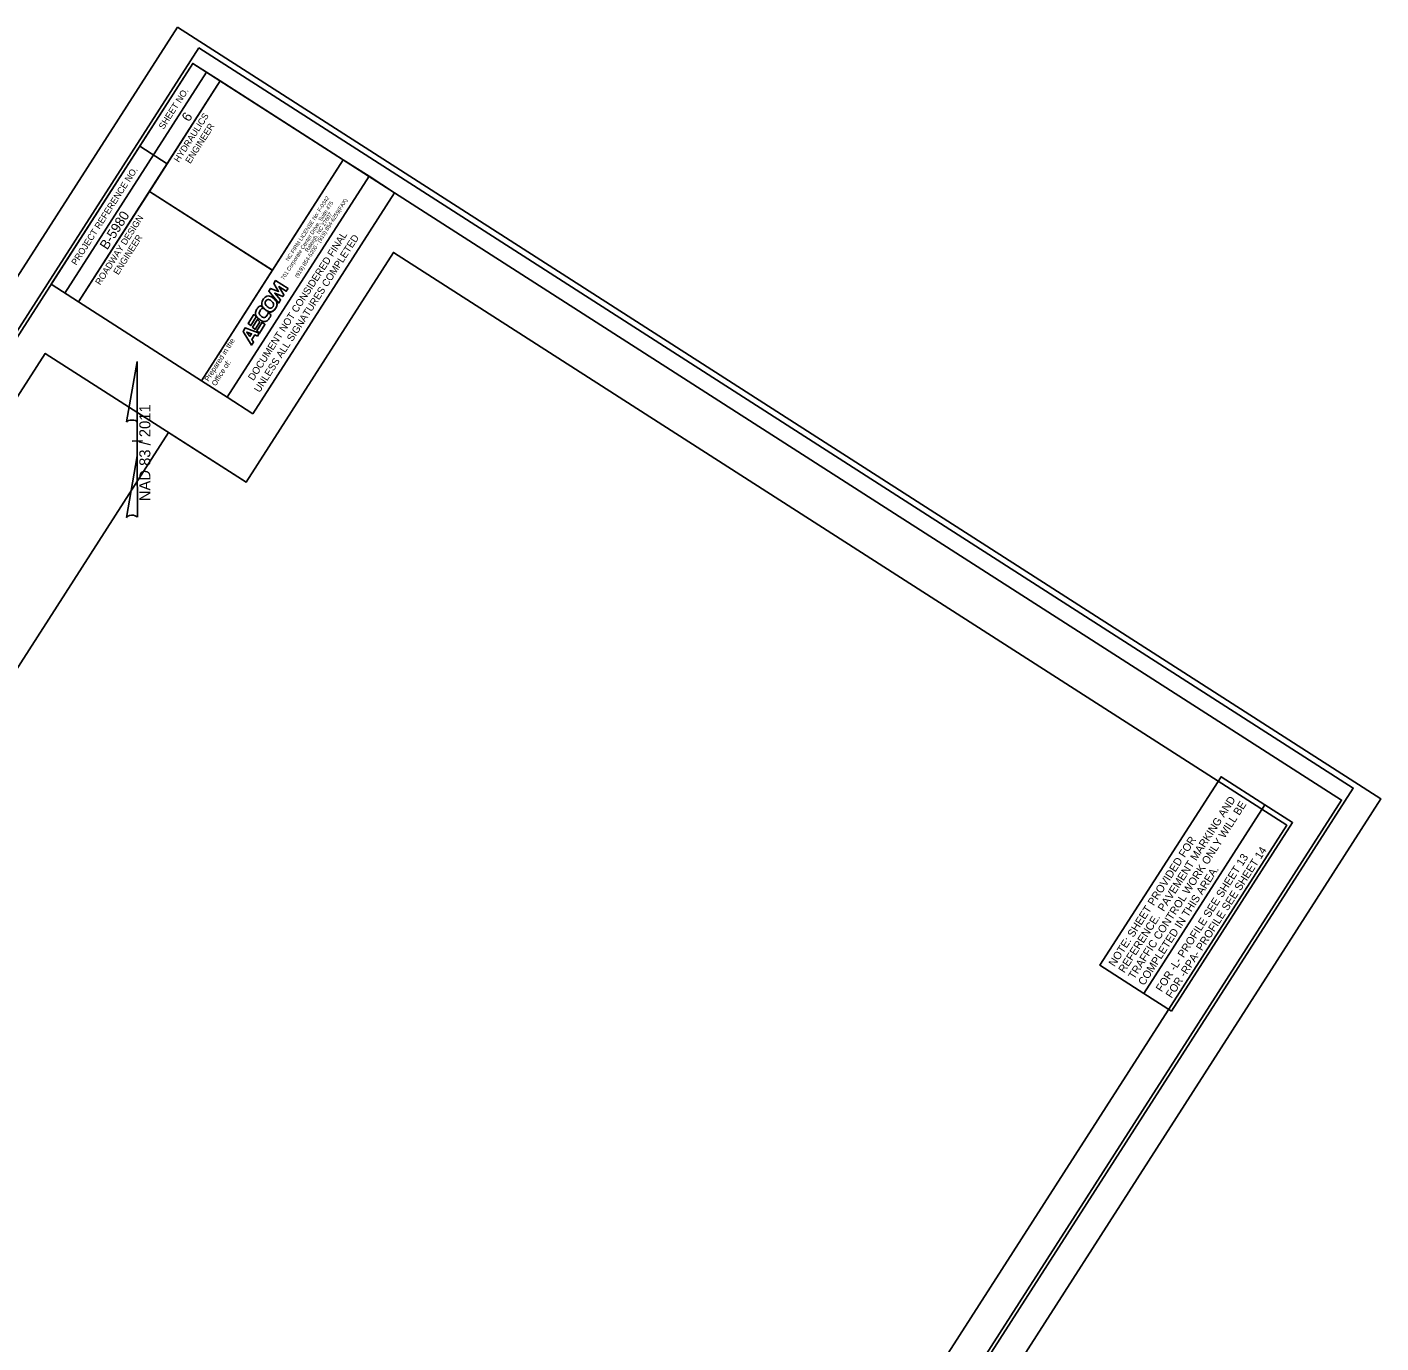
# Model space of a CAD drawing. Extents: x 2348257 to 2350100, y 844892 to 846917.
# Drawn here: x 2349059 to 2350100, y 845904 to 846917 of the extents above; entities that cross this region are included whole.
import ezdxf

# ---------------------------------------------------------------- set-up
doc = ezdxf.new("R2010")
doc.units = 0
for name, color, linetype in [('Default', 7, 'Continuous'), ('Old_Level_49', 7, 'Continuous'), ('Prop DSN Text', 7, 'Continuous'), ('Prop North Arrow NAD83 for Plan Sheets CELL', 7, 'Continuous'), ('Prop PFL Text', 7, 'Continuous'), ('Sheet Border Standard 30in CELL', 7, 'Continuous'), ('Sheet Clip Boundary CELL', 7, 'Continuous'), ('Sheet Data Field CELL', 7, 'Continuous'), ('Sheet Plot Border Inside CELL', 7, 'Continuous'), ('Sheet Plot Border Outside CELL', 7, 'Continuous'), ('Sheet Profile CELL', 7, 'Continuous'), ('Sheet Sticker Exception Certification CELL', 7, 'Continuous')]:
    doc.layers.add(name, color=color, linetype=linetype)

# ---------------------------------------------------------------- blocks, each defined once
blk = doc.blocks.new('block 2')
at = {"layer": 'Default'}
for p, q in [((0.10137, 0.08733), (0.10174, 0.08975)), ((0.10782, 0.08733), (0.10137, 0.08733)), ((0.10174, 0.08975), (0.10818, 0.08975)), ((0.10234, 0.09375), (0.10197, 0.09133)), ((0.10197, 0.09133), (0.10929, 0.09133)), ((0.10966, 0.09375), (0.10234, 0.09375)), ((0.10818, 0.08975), (0.10782, 0.08733)), ((0.10929, 0.09133), (0.10966, 0.09375)), ((0.10114, 0.08576), (0.10078, 0.08333)), ((0.10078, 0.08333), (0.1081, 0.08333)), ((0.10846, 0.08576), (0.10114, 0.08576)), ((0.1081, 0.08333), (0.10846, 0.08576))]:
    blk.add_line(p, q, dxfattribs=at)
for points in [[(0.10782, 0.08733), (0.10137, 0.08733), (0.10174, 0.08975), (0.10818, 0.08975), (0.10782, 0.08733)], [(0.10929, 0.09133), (0.10197, 0.09133), (0.10234, 0.09375), (0.10966, 0.09375), (0.10929, 0.09133)], [(0.10846, 0.08576), (0.10114, 0.08576), (0.10078, 0.08333), (0.1081, 0.08333), (0.10846, 0.08576)]]:
    blk.add_lwpolyline(points, dxfattribs=at)
blk = doc.blocks.new('block 3')
at = {"layer": 'Default'}
blk.add_open_spline([(0.12275, 0.09393), (0.12554, 0.09373), (0.12726, 0.09146), (0.12695, 0.08843), (0.12663, 0.08531), (0.12411, 0.08298), (0.12127, 0.08318), (0.11848, 0.08338), (0.11676, 0.08565), (0.11707, 0.08868), (0.11739, 0.0918), (0.11991, 0.09413), (0.12275, 0.09393)], degree=3, dxfattribs=at)

msp = doc.modelspace()

# ---------------------------------------------------------------- linework, layer by layer
at = {"layer": 'Default'}
for p, q in [((2349212.6, 846632), (2349321.7, 846802)), ((2349232.4, 846619.3), (2349341.4, 846789.3))]:
    msp.add_line(p, q, dxfattribs=at)
at = {"layer": 'Old_Level_49'}
for p, q in [((2349249.8, 846721.7), (2349248.4, 846719.6)), ((2349259.4, 846715.8), (2349249.8, 846721.7)), ((2349246, 846715.7), (2349244.6, 846713.6)), ((2349244.6, 846713.6), (2349252.2, 846704.5)), ((2349252.1, 846713.4), (2349246, 846715.7)), ((2349248.4, 846719.6), (2349252.1, 846713.4)), ((2349253.7, 846706.9), (2349249.2, 846712.1)), ((2349249.2, 846712.1), (2349255.4, 846709.5)), ((2349256.2, 846710.7), (2349252.4, 846717.1)), ((2349252.4, 846717.1), (2349258, 846713.5)), ((2349258, 846713.5), (2349259.4, 846715.8)), ((2349252.2, 846704.5), (2349253.7, 846706.9)), ((2349255.4, 846709.5), (2349256.2, 846710.7)), ((2349226.4, 846685.3), (2349224.8, 846682.7)), ((2349224.8, 846682.7), (2349231.4, 846672.1)), ((2349237.3, 846681.4), (2349226.4, 846685.3)), ((2349230.1, 846678.7), (2349227.6, 846682.2)), ((2349227.6, 846682.2), (2349227.7, 846682.2)), ((2349227.7, 846682.2), (2349231.4, 846680.8)), ((2349231.4, 846680.8), (2349230.1, 846678.7)), ((2349231.6, 846676.5), (2349233.8, 846679.9)), ((2349233.8, 846679.9), (2349235.9, 846679.1)), ((2349235.9, 846679.1), (2349237.3, 846681.4)), ((2349231.4, 846672.1), (2349232.9, 846674.5)), ((2349232.9, 846674.5), (2349231.6, 846676.5))]:
    msp.add_line(p, q, dxfattribs=at)
for points in [[(2349259.4, 846715.8), (2349249.8, 846721.7), (2349248.4, 846719.6), (2349252.1, 846713.4), (2349246, 846715.7), (2349244.6, 846713.6), (2349252.2, 846704.5), (2349253.7, 846706.9), (2349249.2, 846712.1), (2349255.4, 846709.5), (2349256.2, 846710.7), (2349252.4, 846717.1), (2349258, 846713.5), (2349259.4, 846715.8)], [(2349235.9, 846679.1), (2349237.3, 846681.4), (2349226.4, 846685.3), (2349224.8, 846682.7), (2349231.4, 846672.1), (2349232.9, 846674.5), (2349231.6, 846676.5), (2349233.8, 846679.9), (2349235.9, 846679.1)], [(2349230.1, 846678.7), (2349227.6, 846682.2), (2349227.7, 846682.2), (2349231.4, 846680.8), (2349230.1, 846678.7)]]:
    msp.add_lwpolyline(points, dxfattribs=at)
for points in [[(2349244.1, 846697.3), (2349244, 846696.5), (2349243.4, 846695.5), (2349243.2, 846695), (2349242.2, 846693.5), (2349240.5, 846693.2), (2349239, 846694.2), (2349237.4, 846695.3), (2349237.1, 846697.3), (2349238.1, 846698.9), (2349238.6, 846699.7), (2349239.3, 846700.2), (2349240.3, 846700.5), (2349240.3, 846700.5), (2349238.3, 846702.4), (2349238.3, 846702.4), (2349237.1, 846701.8), (2349236.4, 846701.2), (2349235.7, 846700.2), (2349234, 846697.5), (2349234.8, 846693.7), (2349237.6, 846691.8), (2349240.3, 846689.9), (2349243.5, 846690.5), (2349245.2, 846693.2), (2349245.5, 846693.6), (2349246.1, 846694.7), (2349246.2, 846695.5), (2349246.2, 846695.5), (2349244.1, 846697.3), (2349244.1, 846697.3)], [(2349244.1, 846697.3), (2349244, 846696.5), (2349243.4, 846695.5), (2349243.2, 846695), (2349242.2, 846693.5), (2349240.5, 846693.2), (2349239, 846694.2), (2349237.4, 846695.3), (2349237.1, 846697.3), (2349238.1, 846698.9), (2349238.6, 846699.7), (2349239.3, 846700.2), (2349240.3, 846700.5), (2349240.3, 846700.5), (2349238.3, 846702.4), (2349238.3, 846702.4), (2349237.1, 846701.8), (2349236.4, 846701.2), (2349235.7, 846700.2), (2349234, 846697.5), (2349234.8, 846693.7), (2349237.6, 846691.8), (2349240.3, 846689.9), (2349243.5, 846690.5), (2349245.2, 846693.2), (2349245.5, 846693.6), (2349246.1, 846694.7), (2349246.2, 846695.5), (2349246.2, 846695.5), (2349244.1, 846697.3), (2349244.1, 846697.3)], [(2349248.7, 846699.1), (2349246.8, 846697.5), (2349244.2, 846697.6), (2349242, 846699.4), (2349239.3, 846701.5), (2349238.7, 846705.1), (2349240.5, 846707.6)], [(2349240.5, 846707.6), (2349242.3, 846710.1), (2349245.4, 846710.3), (2349248, 846708.2), (2349250.7, 846706.1), (2349251.3, 846702.5), (2349249.5, 846700), (2349249.2, 846699.6), (2349249, 846699.4), (2349248.7, 846699.1)], [(2349246.8, 846705.8), (2349245.4, 846707.2), (2349243.8, 846707.4), (2349242.7, 846706.4), (2349241.6, 846705.2), (2349241.9, 846703.3), (2349243.3, 846701.9), (2349244.7, 846700.5), (2349246.3, 846700.3), (2349247.4, 846701.3), (2349248.5, 846702.5), (2349248.3, 846704.4), (2349246.8, 846705.8)], [(2349246.8, 846705.8), (2349245.4, 846707.2), (2349243.8, 846707.4), (2349242.7, 846706.4), (2349241.6, 846705.2), (2349241.9, 846703.3), (2349243.3, 846701.9), (2349244.7, 846700.5), (2349246.3, 846700.3), (2349247.4, 846701.3), (2349248.5, 846702.5), (2349248.3, 846704.4), (2349246.8, 846705.8)]]:
    msp.add_open_spline(points, degree=3, dxfattribs=at)
at = {"layer": 'Prop North Arrow NAD83 for Plan Sheets CELL'}
for p, q in [((2349135.2, 846613), (2349143.4, 846659.4)), ((2349143.4, 846659.4), (2349143.4, 846611.6)), ((2349143.4, 846586.8), (2349143.4, 846613)), ((2349143.4, 846611.6), (2349143.4, 846612.9)), ((2349143, 846598.4), (2349139.4, 846598.3)), ((2349139.4, 846598.3), (2349139.4, 846598.3)), ((2349139.5, 846598.3), (2349147.5, 846598.4)), ((2349143.4, 846586.8), (2349135.1, 846539.5)), ((2349143.5, 846539.7), (2349143.4, 846586.8))]:
    msp.add_line(p, q, dxfattribs=at)
for centre, start_param, end_param in [((2349139.3, 846612.5), 0.211319, 2.90315), ((2349139.3, 846539.3), 0.19626, 3.136524)]:
    msp.add_ellipse(centre, major_axis=(4.23, 0.02), ratio=0.461128, start_param=start_param, end_param=end_param, dxfattribs=at)
at = {"layer": 'Prop PFL Text'}
for points in [[(2349917.9, 846173.3), (2350010.9, 846318.4), (2349977.2, 846340), (2349884.1, 846195)], [(2349939.2, 846159.6), (2350032.3, 846304.7), (2350010.9, 846318.4), (2349917.9, 846173.3)]]:
    msp.add_lwpolyline(points, close=True, dxfattribs=at)
at = {"layer": 'Sheet Border Standard 30in CELL'}
for p, q in [((2349087.6, 846712.1), (2349196.7, 846882.1)), ((2349098.2, 846705.4), (2349207.2, 846875.4)), ((2349098.2, 846705.4), (2349207.2, 846875.4)), ((2349145.3, 846825.2), (2349166.3, 846811.7)), ((2349152.7, 846790.4), (2349247.3, 846729.7)), ((2349152.7, 846790.4), (2349247.3, 846729.7))]:
    msp.add_line(p, q, dxfattribs=at)
for points in [[(2349186.1, 846888.9), (2348368.6, 845614.2), (2349252.5, 845047.4), (2350070, 846322.1)], [(2349077.1, 846718.9), (2349186.1, 846888.9), (2349207.2, 846875.4), (2349098.2, 846705.4)], [(2349152.7, 846790.4), (2349207.2, 846875.4), (2349301.9, 846814.7), (2349247.4, 846729.7)], [(2349098.2, 846705.4), (2349152.7, 846790.4), (2349247.4, 846729.7), (2349192.9, 846644.7)]]:
    msp.add_lwpolyline(points, close=True, dxfattribs=at)
at = {"layer": 'Sheet Clip Boundary CELL'}
for points in [[(2348430.6, 845664.6), (2349272.4, 845124.8), (2350027.8, 846302.7), (2349340.5, 846743.4), (2349227.1, 846566.6), (2349072.6, 846665.7)], [(2348885.9, 846374.5), (2348430.6, 845664.6), (2349272.4, 845124.8), (2350027.8, 846302.7), (2349340.5, 846743.4), (2349227.1, 846566.6), (2349167.4, 846604.9), (2348974.4, 846304)]]:
    msp.add_lwpolyline(points, close=True, dxfattribs=at)
at = {"layer": 'Sheet Plot Border Inside CELL'}
msp.add_lwpolyline([(2349190.8, 846900.9), (2348282.5, 845484.7), (2349170.7, 844915.1), (2350078.9, 846331.3)], close=True, dxfattribs=at)
at = {"layer": 'Sheet Plot Border Outside CELL'}
msp.add_lwpolyline([(2349174.3, 846916.8), (2348256.6, 845485.8), (2349182.5, 844892), (2350100.2, 846323)], close=True, dxfattribs=at)
at = {"layer": 'Sheet Profile CELL'}
msp.add_line((2349192.9, 846644.7), (2349212.6, 846632), dxfattribs=at)
at = {"layer": 'Sheet Sticker Exception Certification CELL'}
for p, q in [((2349192.9, 846644.7), (2349301.9, 846814.7)), ((2349301.9, 846814.6), (2349321.7, 846802)), ((2349321.7, 846802), (2349212.6, 846632)), ((2349212.6, 846632), (2349321.7, 846802)), ((2349321.7, 846802), (2349341.4, 846789.3)), ((2349341.4, 846789.3), (2349232.4, 846619.3)), ((2349212.6, 846632), (2349192.9, 846644.7)), ((2349232.4, 846619.3), (2349212.6, 846632))]:
    msp.add_line(p, q, dxfattribs=at)

# ---------------------------------------------------------------- block references
at = {"layer": 'Old_Level_49', "xscale": 1084.8432715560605, "yscale": 1084.8432715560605, "rotation": 57.32454195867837}
for name in ['block 3', 'block 2']:
    msp.add_blockref(name, (2349254.4, 846540.5), dxfattribs=at)

# ---------------------------------------------------------------- texts
at = {"layer": 'Old_Level_49'}
for s, height, p in [('NC FIRM LICENSE No: F-0342', 3.013, (2349259.9, 846736.4)), ('701 Corporate Center Drive, Suite 475', 3.013, (2349256.2, 846722)), ('(919) 854-6200 - (919) 854-6259(FAX)', 3.013, (2349266.8, 846723.6)), ('Raleigh, NC 27607', 3.013, (2349274.7, 846743.4)), ('Prepared in the ', 4.018, (2349198.2, 846643.8)), ('Office of:', 4.02, (2349203.7, 846640.3))]:
    msp.add_text(s, height=height, rotation=57.3245, dxfattribs=at).set_placement(p)
at = {"layer": 'Prop DSN Text'}
for s, p in [('REFERENCE.  PAVEMENT MARKING AND ', (2349902.8, 846188.6)), ('TRAFFIC CONTROL WORK ONLY WILL BE ', (2349910.4, 846183.7)), ('NOTE: SHEET PROVIDED FOR ', (2349895.3, 846193.4)), ('FOR -RPA- PROFILE SEE SHEET 14', (2349939.2, 846169.2)), ('FOR -L- PROFILE SEE SHEET 13', (2349931.6, 846174)), ('COMPLETED IN THIS AREA.', (2349918, 846178.9))]:
    msp.add_text(s, height=6, rotation=57.3281, dxfattribs=at).set_placement(p)
at = {"layer": 'Prop North Arrow NAD83 for Plan Sheets CELL'}
msp.add_text('NAD 83 / 2011', height=8.501, rotation=90, dxfattribs=at).set_placement((2349153.5, 846552))
at = {"layer": 'Sheet Border Standard 30in CELL'}
for s, p in [('SHEET NO.', (2349163.7, 846837.7)), ('HYDRAULICS', (2349175.4, 846812.3)), ('ENGINEER', (2349184.2, 846811.3)), ('PROJECT REFERENCE NO.', (2349096.5, 846733.1)), ('ROADWAY DESIGN', (2349114.9, 846717.9)), ('ENGINEER', (2349128.8, 846725.7))]:
    msp.add_text(s, height=5, rotation=57.3281, dxfattribs=at).set_placement(p)
at = {"layer": 'Sheet Data Field CELL'}
for s, p in [('6', (2349183.3, 846843.4)), ('B-5980', (2349120.3, 846744.9))]:
    msp.add_text(s, height=7.5, rotation=57.3281, dxfattribs=at).set_placement(p)
at = {"layer": 'Sheet Sticker Exception Certification CELL'}
for s, p in [('DOCUMENT NOT CONSIDERED FINAL', (2349232.8, 846644.3)), ('UNLESS ALL SIGNATURES COMPLETED', (2349237.5, 846635.2))]:
    msp.add_text(s, height=5.5, rotation=57.3281, dxfattribs=at).set_placement(p)

doc.saveas('drawing.dxf')
